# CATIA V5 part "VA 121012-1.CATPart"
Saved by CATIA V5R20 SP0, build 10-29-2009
Part number: VA 121012-1
Revision: ANY
Definition: UNKNOWN
Nomenclature: VA 121012-1
Source: Unknown
Bounding box of the stored display mesh (mm): x -4.955 to 4.955, y 0 to 10.3, z -4.955 to 4.955
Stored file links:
  C:\Users\Utente\Desktop\IO LAVORO\3D X SITO CF\CUMSA\3D files VA\VA 121012\VA 121012-1.CATPart
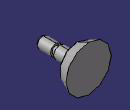
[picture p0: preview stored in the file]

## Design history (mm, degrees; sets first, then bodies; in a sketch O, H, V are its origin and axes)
Body1 "Chaflán1" (main body)
  Solid1: solid without history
